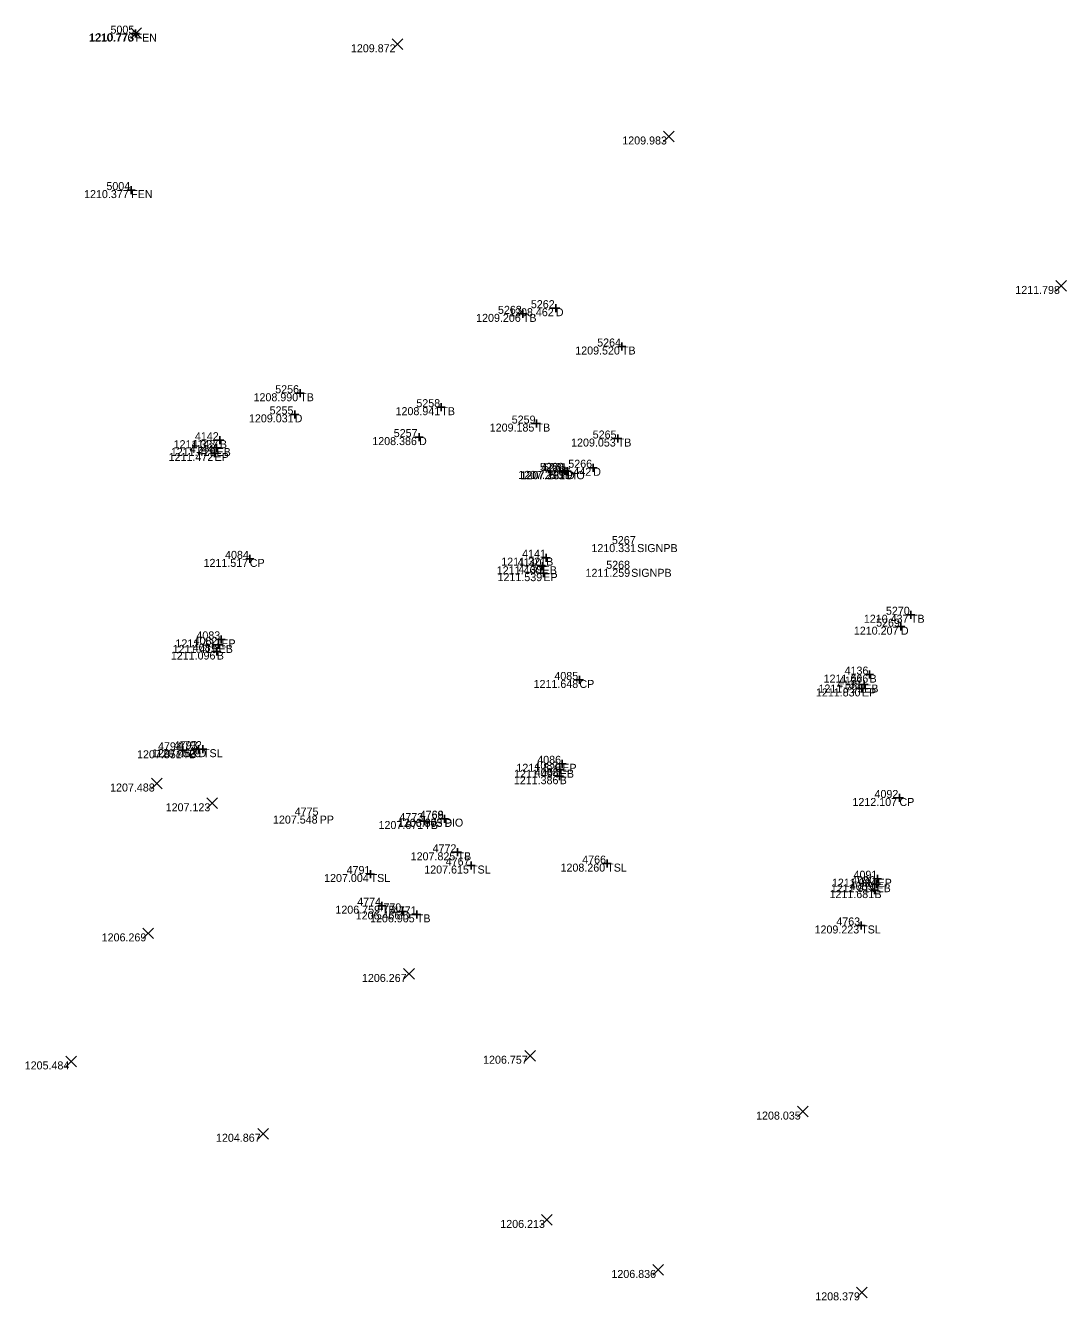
# Model space of a CAD drawing. Extents: x 2044997 to 2050342, y 455233 to 458054.
# Drawn here: x 2048265.8 to 2048395.9, y 456662 to 456821.3 of the extents above; entities that cross this region are included whole.
import ezdxf

# ---------------------------------------------------------------- set-up
doc = ezdxf.new("R2010")
doc.units = 0
for name, color, linetype in [('SV_X_Random_Point', 7, 'Continuous'), ('SV_X_Shot_Marker', 7, 'Continuous'), ('SV_X_Text_Comment', 7, 'Continuous'), ('SV_X_Text_Elevation', 7, 'Continuous'), ('SV_X_Text_Name', 7, 'Continuous')]:
    doc.layers.add(name, color=color, linetype=linetype)

msp = doc.modelspace()

# ---------------------------------------------------------------- linework, layer by layer
at = {"layer": 'SV_X_Random_Point'}
for p, q in [((2048278.98, 456819.65), (2048280.32, 456820.99)), ((2048278.98, 456820.99), (2048280.32, 456819.65)), ((2048311.67, 456818.27), (2048313, 456819.61)), ((2048311.67, 456819.61), (2048313, 456818.27)), ((2048345.58, 456806.76), (2048346.92, 456808.09)), ((2048345.58, 456808.09), (2048346.92, 456806.76)), ((2048394.6, 456788.08), (2048395.94, 456789.41)), ((2048394.6, 456789.41), (2048395.94, 456788.08)), ((2048281.57, 456725.9), (2048282.9, 456727.23)), ((2048281.57, 456727.23), (2048282.9, 456725.9)), ((2048288.51, 456723.43), (2048289.84, 456724.76)), ((2048288.51, 456724.76), (2048289.84, 456723.43)), ((2048280.5, 456707.17), (2048281.84, 456708.5)), ((2048280.5, 456708.5), (2048281.84, 456707.17)), ((2048313.09, 456702.09), (2048314.43, 456703.43)), ((2048313.09, 456703.43), (2048314.43, 456702.09)), ((2048270.87, 456691.16), (2048272.2, 456692.5)), ((2048270.87, 456692.5), (2048272.2, 456691.16)), ((2048328.23, 456691.87), (2048329.56, 456693.21)), ((2048328.23, 456693.21), (2048329.56, 456691.87)), ((2048362.32, 456684.9), (2048363.65, 456686.23)), ((2048362.32, 456686.23), (2048363.65, 456684.9)), ((2048294.85, 456682.12), (2048296.18, 456683.45)), ((2048294.85, 456683.45), (2048296.18, 456682.12)), ((2048330.33, 456671.35), (2048331.66, 456672.68)), ((2048330.33, 456672.68), (2048331.66, 456671.35)), ((2048344.23, 456665.1), (2048345.56, 456666.44)), ((2048344.23, 456666.44), (2048345.56, 456665.1)), ((2048369.69, 456662.3), (2048371.03, 456663.63)), ((2048369.69, 456663.63), (2048371.03, 456662.3))]:
    msp.add_line(p, q, dxfattribs=at)
at = {"layer": 'SV_X_Shot_Marker'}
for p, q in [((2048279.08, 456820.27), (2048280.08, 456820.27)), ((2048279.58, 456820.77), (2048279.58, 456819.77)), ((2048279.58, 456820.27), (2048279.58, 456820.27)), ((2048278.53, 456800.72), (2048279.53, 456800.72)), ((2048279.03, 456801.22), (2048279.03, 456800.22)), ((2048279.03, 456800.72), (2048279.03, 456800.72)), ((2048331.61, 456785.96), (2048332.61, 456785.96)), ((2048332.11, 456786.46), (2048332.11, 456785.46)), ((2048332.11, 456785.96), (2048332.11, 456785.96)), ((2048327.49, 456785.25), (2048328.49, 456785.25)), ((2048327.99, 456785.75), (2048327.99, 456784.75)), ((2048327.99, 456785.25), (2048327.99, 456785.25)), ((2048339.87, 456781.17), (2048340.87, 456781.17)), ((2048340.37, 456781.67), (2048340.37, 456780.67)), ((2048340.37, 456781.17), (2048340.37, 456781.17)), ((2048299.66, 456775.33), (2048300.66, 456775.33)), ((2048300.16, 456775.83), (2048300.16, 456774.83)), ((2048300.16, 456775.33), (2048300.16, 456775.33)), ((2048299.47, 456773.19), (2048299.47, 456772.19)), ((2048317.3, 456773.59), (2048318.3, 456773.59)), ((2048317.8, 456774.09), (2048317.8, 456773.09)), ((2048317.8, 456773.59), (2048317.8, 456773.59)), ((2048298.97, 456772.69), (2048299.97, 456772.69)), ((2048299.47, 456772.69), (2048299.47, 456772.69)), ((2048329.7, 456772.04), (2048329.7, 456771.04)), ((2048290.12, 456769.96), (2048290.12, 456768.96)), ((2048315.01, 456770.35), (2048315.01, 456769.35)), ((2048329.2, 456771.54), (2048330.2, 456771.54)), ((2048329.7, 456771.54), (2048329.7, 456771.54)), ((2048339.85, 456770.17), (2048339.85, 456769.17)), ((2048289.2, 456768.49), (2048290.2, 456768.49)), ((2048289.62, 456769.46), (2048290.62, 456769.46)), ((2048289.7, 456768.99), (2048289.7, 456767.99)), ((2048289.7, 456768.49), (2048289.7, 456768.49)), ((2048290.12, 456769.46), (2048290.12, 456769.46)), ((2048314.51, 456769.85), (2048315.51, 456769.85)), ((2048315.01, 456769.85), (2048315.01, 456769.85)), ((2048339.35, 456769.67), (2048340.35, 456769.67)), ((2048339.85, 456769.67), (2048339.85, 456769.67)), ((2048288.95, 456767.86), (2048289.95, 456767.86)), ((2048289.45, 456768.36), (2048289.45, 456767.36)), ((2048289.45, 456767.86), (2048289.45, 456767.86)), ((2048332.75, 456765.63), (2048333.75, 456765.63)), ((2048333.01, 456765.59), (2048334.01, 456765.59)), ((2048333.25, 456766.13), (2048333.25, 456765.13)), ((2048333.25, 456765.63), (2048333.25, 456765.63)), ((2048333.51, 456766.09), (2048333.51, 456765.09)), ((2048333.51, 456765.59), (2048333.51, 456765.59)), ((2048336.29, 456766.02), (2048337.29, 456766.02)), ((2048336.79, 456766.52), (2048336.79, 456765.52)), ((2048336.79, 456766.02), (2048336.79, 456766.02)), ((2048293.36, 456754.63), (2048294.36, 456754.63)), ((2048293.86, 456755.13), (2048293.86, 456754.13)), ((2048293.86, 456754.63), (2048293.86, 456754.63)), ((2048330.4, 456754.78), (2048331.4, 456754.78)), ((2048330.46, 456754.21), (2048330.46, 456753.21)), ((2048330.9, 456755.28), (2048330.9, 456754.28)), ((2048330.9, 456754.78), (2048330.9, 456754.78)), ((2048329.96, 456753.71), (2048330.96, 456753.71)), ((2048330.05, 456752.85), (2048331.05, 456752.85)), ((2048330.46, 456753.71), (2048330.46, 456753.71)), ((2048330.55, 456753.35), (2048330.55, 456752.35)), ((2048330.55, 456752.85), (2048330.55, 456752.85)), ((2048375.99, 456747.65), (2048376.99, 456747.65)), ((2048376.49, 456748.15), (2048376.49, 456747.15)), ((2048376.49, 456747.65), (2048376.49, 456747.65)), ((2048374.74, 456746.16), (2048375.74, 456746.16)), ((2048375.24, 456746.66), (2048375.24, 456745.66)), ((2048375.24, 456746.16), (2048375.24, 456746.16)), ((2048289.8, 456744.57), (2048290.8, 456744.57)), ((2048290.3, 456745.07), (2048290.3, 456744.07)), ((2048290.3, 456744.57), (2048290.3, 456744.57)), ((2048289.23, 456743.05), (2048290.23, 456743.05)), ((2048289.46, 456743.88), (2048290.46, 456743.88)), ((2048289.73, 456743.55), (2048289.73, 456742.55)), ((2048289.73, 456743.05), (2048289.73, 456743.05)), ((2048289.96, 456744.38), (2048289.96, 456743.38)), ((2048289.96, 456743.88), (2048289.96, 456743.88)), ((2048335.06, 456740), (2048335.06, 456739)), ((2048370.82, 456740.17), (2048371.82, 456740.17)), ((2048371.32, 456740.67), (2048371.32, 456739.67)), ((2048371.32, 456740.17), (2048371.32, 456740.17)), ((2048334.56, 456739.5), (2048335.56, 456739.5)), ((2048335.06, 456739.5), (2048335.06, 456739.5)), ((2048369.86, 456738.44), (2048370.86, 456738.44)), ((2048370.15, 456738.93), (2048371.15, 456738.93)), ((2048370.36, 456738.94), (2048370.36, 456737.94)), ((2048370.36, 456738.44), (2048370.36, 456738.44)), ((2048370.65, 456739.43), (2048370.65, 456738.43)), ((2048370.65, 456738.93), (2048370.65, 456738.93)), ((2048284.98, 456730.71), (2048285.98, 456730.71)), ((2048285.48, 456731.21), (2048285.48, 456730.21)), ((2048285.48, 456730.71), (2048285.48, 456730.71)), ((2048286.96, 456730.85), (2048287.96, 456730.85)), ((2048287.46, 456731.35), (2048287.46, 456730.35)), ((2048287.46, 456730.85), (2048287.46, 456730.85)), ((2048287.51, 456730.85), (2048288.51, 456730.85)), ((2048288.01, 456731.35), (2048288.01, 456730.35)), ((2048288.01, 456730.85), (2048288.01, 456730.85)), ((2048332.42, 456729.02), (2048333.42, 456729.02)), ((2048332.6, 456728.79), (2048332.6, 456727.79)), ((2048332.92, 456729.52), (2048332.92, 456728.52)), ((2048332.92, 456729.02), (2048332.92, 456729.02)), ((2048332.09, 456727.47), (2048333.09, 456727.47)), ((2048332.1, 456728.29), (2048333.1, 456728.29)), ((2048332.59, 456727.97), (2048332.59, 456726.97)), ((2048332.59, 456727.47), (2048332.59, 456727.47)), ((2048332.6, 456728.29), (2048332.6, 456728.29)), ((2048374.56, 456724.75), (2048375.56, 456724.75)), ((2048375.06, 456725.25), (2048375.06, 456724.25)), ((2048375.06, 456724.75), (2048375.06, 456724.75)), ((2048315.67, 456722.37), (2048315.67, 456721.37)), ((2048318.19, 456722.63), (2048318.19, 456721.63)), ((2048315.17, 456721.87), (2048316.17, 456721.87)), ((2048315.67, 456721.87), (2048315.67, 456721.87)), ((2048317.69, 456722.13), (2048318.69, 456722.13)), ((2048318.19, 456722.13), (2048318.19, 456722.13)), ((2048319.32, 456717.96), (2048320.32, 456717.96)), ((2048319.82, 456718.46), (2048319.82, 456717.46)), ((2048319.82, 456717.96), (2048319.82, 456717.96)), ((2048321.01, 456716.31), (2048322.01, 456716.31)), ((2048321.51, 456716.81), (2048321.51, 456715.81)), ((2048321.51, 456716.31), (2048321.51, 456716.31)), ((2048338.03, 456716.55), (2048339.03, 456716.55)), ((2048338.53, 456717.05), (2048338.53, 456716.05)), ((2048338.53, 456716.55), (2048338.53, 456716.55)), ((2048308.46, 456715.25), (2048309.46, 456715.25)), ((2048308.96, 456715.75), (2048308.96, 456714.75)), ((2048308.96, 456715.25), (2048308.96, 456715.25)), ((2048371.82, 456714.66), (2048372.82, 456714.66)), ((2048372.19, 456714.48), (2048372.19, 456713.48)), ((2048372.32, 456715.16), (2048372.32, 456714.16)), ((2048372.32, 456714.66), (2048372.32, 456714.66)), ((2048371.44, 456713.24), (2048372.44, 456713.24)), ((2048371.69, 456713.98), (2048372.69, 456713.98)), ((2048371.94, 456713.74), (2048371.94, 456712.74)), ((2048371.94, 456713.24), (2048371.94, 456713.24)), ((2048372.19, 456713.98), (2048372.19, 456713.98)), ((2048309.88, 456711.29), (2048310.88, 456711.29)), ((2048310.38, 456711.79), (2048310.38, 456710.79)), ((2048310.38, 456711.29), (2048310.38, 456711.29)), ((2048312.94, 456711.08), (2048312.94, 456710.08)), ((2048312.44, 456710.58), (2048313.44, 456710.58)), ((2048312.94, 456710.58), (2048312.94, 456710.58)), ((2048314.24, 456710.21), (2048315.24, 456710.21)), ((2048314.74, 456710.71), (2048314.74, 456709.71)), ((2048314.74, 456710.21), (2048314.74, 456710.21)), ((2048369.77, 456708.82), (2048370.77, 456708.82)), ((2048370.27, 456709.32), (2048370.27, 456708.32)), ((2048370.27, 456708.82), (2048370.27, 456708.82))]:
    msp.add_line(p, q, dxfattribs=at)

# ---------------------------------------------------------------- texts
at = {"layer": 'SV_X_Text_Comment'}
for s, p in [('FEN', (2048279.58, 456819.27)), ('FEN', (2048279.03, 456799.72)), ('D', (2048332.11, 456784.96)), ('TB', (2048327.99, 456784.25)), ('TB', (2048340.37, 456780.17)), ('TB', (2048300.16, 456774.33)), ('TB', (2048317.8, 456772.59)), ('D', (2048299.47, 456771.69)), ('TB', (2048329.7, 456770.54)), ('EB', (2048289.7, 456767.49)), ('B', (2048290.12, 456768.46)), ('D', (2048315.01, 456768.85)), ('TB', (2048339.85, 456768.67)), ('EP', (2048289.45, 456766.86)), ('D', (2048333.25, 456764.63)), ('PIO', (2048333.42, 456764.58)), ('D', (2048333.51, 456764.59)), ('D', (2048336.79, 456765.02)), ('SIGNPB', (2048342.28, 456755.48)), ('CP', (2048293.86, 456753.63)), ('B', (2048330.9, 456753.78)), ('EB', (2048330.46, 456752.71)), ('EP', (2048330.55, 456751.85)), ('SIGNPB', (2048341.53, 456752.39)), ('TB', (2048376.49, 456746.65)), ('D', (2048375.24, 456745.16)), ('EP', (2048290.3, 456743.57)), ('B', (2048289.73, 456742.05)), ('EB', (2048289.96, 456742.88)), ('B', (2048371.32, 456739.17)), ('CP', (2048335.06, 456738.5)), ('EP', (2048370.36, 456737.44)), ('EB', (2048370.65, 456737.93)), ('TB', (2048285.48, 456729.71)), ('D', (2048287.46, 456729.85)), ('TSL', (2048288.01, 456729.85)), ('EP', (2048332.92, 456728.02)), ('B', (2048332.59, 456726.47)), ('EB', (2048332.6, 456727.29)), ('CP', (2048375.06, 456723.75)), ('PP', (2048302.6, 456721.55)), ('PIO', (2048318.23, 456721.17)), ('TB', (2048315.67, 456720.87)), ('D', (2048318.19, 456721.13)), ('TB', (2048319.82, 456716.96)), ('TSL', (2048321.51, 456715.31)), ('TSL', (2048338.53, 456715.55)), ('TSL', (2048308.96, 456714.25)), ('EP', (2048372.32, 456713.66)), ('B', (2048371.94, 456712.24)), ('EB', (2048372.19, 456712.98)), ('TB', (2048310.38, 456710.29)), ('D', (2048312.94, 456709.58)), ('TB', (2048314.74, 456709.21)), ('TSL', (2048370.27, 456707.82))]:
    msp.add_text(s, height=1, dxfattribs=at).set_placement(p)
at = {"layer": 'SV_X_Text_Elevation'}
for s, p in [('1210.776', (2048273.74, 456819.27)), ('1210.773', (2048273.83, 456819.32)), ('1209.872', (2048306.5, 456817.94)), ('1209.983', (2048340.42, 456806.42)), ('1210.377', (2048273.15, 456799.72)), ('1211.798', (2048389.54, 456787.74)), ('1208.462', (2048326.27, 456784.96)), ('1209.206', (2048322.15, 456784.25)), ('1209.520', (2048334.54, 456780.17)), ('1208.990', (2048294.33, 456774.33)), ('1208.941', (2048312.08, 456772.59)), ('1209.031', (2048293.76, 456771.69)), ('1209.185', (2048323.85, 456770.54)), ('1211.429', (2048283.99, 456767.49)), ('1211.337', (2048284.34, 456768.46)), ('1208.386', (2048309.17, 456768.85)), ('1209.053', (2048334.02, 456768.67)), ('1211.472', (2048283.72, 456766.86)), ('1207.250', (2048327.41, 456764.63)), ('1207.285', (2048327.66, 456764.59)), ('1207.181', (2048327.71, 456764.58)), ('1207.442', (2048330.96, 456765.02)), ('1210.331', (2048336.56, 456755.48)), ('1211.517', (2048288.08, 456753.63)), ('1211.321', (2048325.29, 456753.78)), ('1211.460', (2048324.73, 456752.71)), ('1211.539', (2048324.83, 456751.85)), ('1211.259', (2048335.82, 456752.39)), ('1210.437', (2048370.61, 456746.65)), ('1210.207', (2048369.36, 456745.16)), ('1211.432', (2048284.57, 456743.57)), ('1211.096', (2048283.99, 456742.05)), ('1211.415', (2048284.22, 456742.88)), ('1211.666', (2048365.58, 456739.17)), ('1211.648', (2048329.33, 456738.5)), ('1211.830', (2048364.62, 456737.44)), ('1211.799', (2048364.94, 456737.93)), ('1207.851', (2048279.77, 456729.71)), ('1207.463', (2048281.63, 456729.85)), ('1207.529', (2048282.19, 456729.85)), ('1211.526', (2048327.18, 456728.02)), ('1211.386', (2048326.86, 456726.47)), ('1211.494', (2048326.9, 456727.29)), ('1207.488', (2048276.4, 456725.56)), ('1207.123', (2048283.35, 456723.09)), ('1212.107', (2048369.18, 456723.75)), ('1207.548', (2048296.76, 456721.55)), ('1206.875', (2048312.38, 456721.17)), ('1207.671', (2048309.95, 456720.87)), ('1206.903', (2048312.36, 456721.13)), ('1207.825', (2048313.97, 456716.96)), ('1207.615', (2048315.67, 456715.31)), ('1208.260', (2048332.7, 456715.55)), ('1207.004', (2048303.15, 456714.25)), ('1211.984', (2048366.62, 456713.66)), ('1211.681', (2048366.32, 456712.24)), ('1211.919', (2048366.48, 456712.98)), ('1206.759', (2048304.56, 456710.29)), ('1206.466', (2048307.1, 456709.58)), ('1206.905', (2048308.89, 456709.21)), ('1206.269', (2048275.35, 456706.83)), ('1209.223', (2048364.45, 456707.82)), ('1206.267', (2048307.88, 456701.76)), ('1206.757', (2048323.02, 456691.54)), ('1205.484', (2048265.73, 456690.83)), ('1208.035', (2048357.14, 456684.56)), ('1204.867', (2048289.64, 456681.79)), ('1206.213', (2048325.17, 456671.02)), ('1206.836', (2048339.06, 456664.77)), ('1208.379', (2048364.54, 456661.97))]:
    msp.add_text(s, height=1, dxfattribs=at).set_placement(p)
at = {"layer": 'SV_X_Text_Name'}
for s, p in [('5005', (2048276.45, 456820.27)), ('5004', (2048275.94, 456800.72)), ('5263', (2048324.88, 456785.25)), ('5262', (2048328.99, 456785.96)), ('5264', (2048337.28, 456781.17)), ('5256', (2048297.04, 456775.33)), ('5255', (2048296.34, 456772.69)), ('5258', (2048314.68, 456773.59)), ('5259', (2048326.6, 456771.54)), ('4142', (2048287, 456769.46)), ('5257', (2048311.85, 456769.85)), ('5265', (2048336.72, 456769.67)), ('4144', (2048286.36, 456767.86)), ('4143', (2048286.59, 456768.49)), ('5266', (2048333.67, 456766.02)), ('5260', (2048330.13, 456765.63)), ('4776', (2048330.3, 456765.58)), ('5261', (2048330.51, 456765.59)), ('5267', (2048339.12, 456756.48)), ('4084', (2048290.77, 456754.63)), ('4141', (2048327.9, 456754.78)), ('4140', (2048327.34, 456753.71)), ('5268', (2048338.41, 456753.39)), ('4139', (2048327.45, 456752.85)), ('5270', (2048373.37, 456747.65)), ('5269', (2048372.14, 456746.16)), ('4082', (2048286.85, 456743.88)), ('4083', (2048287.19, 456744.57)), ('4081', (2048286.73, 456743.05)), ('4085', (2048331.93, 456739.5)), ('4137', (2048367.49, 456738.93)), ('4136', (2048368.2, 456740.17)), ('4138', (2048367.24, 456738.44)), ('4794', (2048282.39, 456730.71)), ('4793', (2048284.35, 456730.85)), ('4792', (2048284.89, 456730.85)), ('4087', (2048329.44, 456728.29)), ('4086', (2048329.79, 456729.02)), ('4088', (2048329.48, 456727.47)), ('4092', (2048371.94, 456724.75)), ('4775', (2048299.47, 456722.55)), ('4773', (2048312.56, 456721.87)), ('4769', (2048315.09, 456722.13)), ('4768', (2048315.11, 456722.17)), ('4772', (2048316.71, 456717.96)), ('4766', (2048335.41, 456716.55)), ('4791', (2048305.96, 456715.25)), ('4767', (2048318.35, 456716.31)), ('4089', (2048368.84, 456713.24)), ('4090', (2048369.07, 456713.98)), ('4091', (2048369.32, 456714.66)), ('4774', (2048307.29, 456711.29)), ('4770', (2048309.82, 456710.58)), ('4771', (2048311.74, 456710.21)), ('4763', (2048367.17, 456708.82))]:
    msp.add_text(s, height=1, dxfattribs=at).set_placement(p)

doc.saveas('drawing.dxf')
